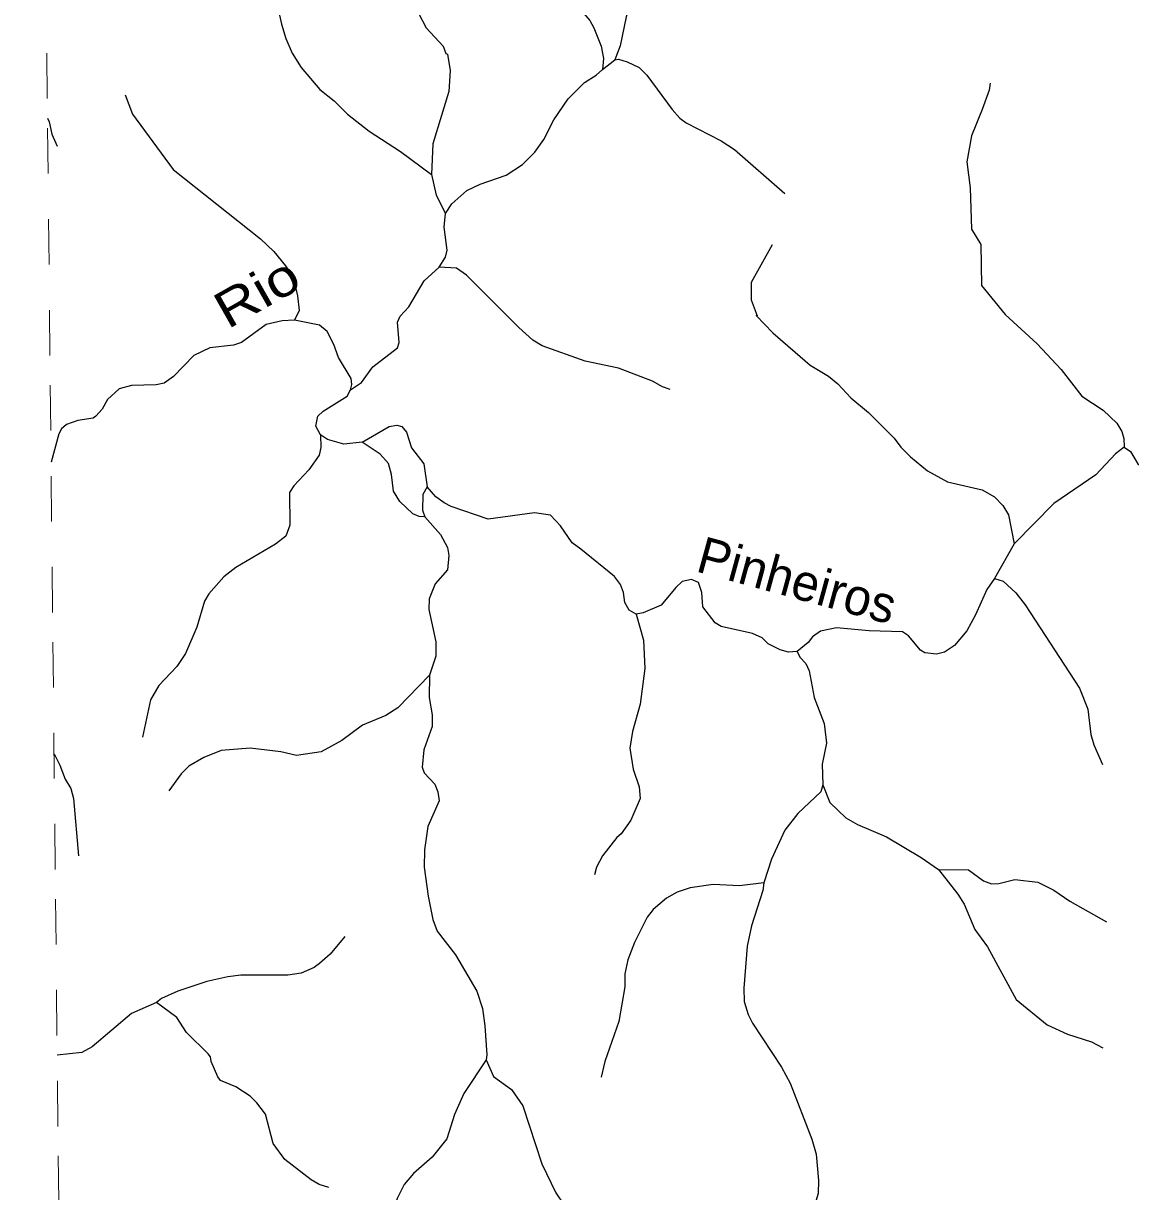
# Model space of a CAD drawing. Extents: x 346.5 to 372.4, y 7400.3 to 7428.2.
# Drawn here: x 346.55 to 348.985, y 7420.515 to 7423.084 of the extents above; entities that cross this region are included whole.
import ezdxf
from ezdxf.enums import TextEntityAlignment as Align

# ---------------------------------------------------------------- set-up
doc = ezdxf.new("R2010")
doc.units = 0
doc.header["$LTSCALE"] = 0.032
doc.linetypes.add('SHORT_DASHED', pattern=[2.7, 1.5, -1.2])
for name, color, linetype, lineweight in [('2', 7, 'Continuous', 25), ('53', 7, 'SHORT_DASHED', 13), ('7', 7, 'Continuous', 25)]:
    doc.layers.add(name, color=color, linetype=linetype, lineweight=lineweight)
doc.layers.add('61', color=7, linetype='Continuous')

msp = doc.modelspace()

# ---------------------------------------------------------------- linework, layer by layer
at = {"layer": '2'}
msp.add_lwpolyline([(347.2945, 7422.163), (347.3542, 7422.1973), (347.3709, 7422.2), (347.3817, 7422.1975), (347.392, 7422.1852), (347.4031, 7422.1505), (347.43, 7422.115), (347.4378, 7422.0645), (347.4279, 7422.0477), (347.4272, 7422.0132), (347.4327, 7421.9988), (347.4198, 7421.9995), (347.4059, 7422.0057), (347.3778, 7422.0327), (347.3637, 7422.0549), (347.3591, 7422.0917), (347.3525, 7422.116), (347.3346, 7422.1365)], close=True, dxfattribs=at)
at = {"layer": '53'}
msp.add_lwpolyline([(346.6314, 7420.0936), (346.6255, 7420.6585), (346.6197, 7421.2235), (346.6138, 7421.7885), (346.608, 7422.3534), (346.6021, 7422.9184), (346.5963, 7423.4833), (346.5904, 7424.0483), (346.5846, 7424.6132), (346.5787, 7425.1782), (346.5729, 7425.7431), (346.567, 7426.3081), (346.5612, 7426.873), (346.5553, 7427.438), (346.5495, 7428.0029)], dxfattribs=at)
at = {"layer": '7'}
for points in [[(347.5316, 7423.518), (347.538, 7423.5013), (347.5826, 7423.4375), (347.6216, 7423.3714), (347.6822, 7423.31), (347.6958, 7423.2813), (347.7205, 7423.1953), (347.7555, 7423.1379), (347.7954, 7423.0901), (347.8041, 7423.0741), (347.8201, 7423.0335), (347.8254, 7423.0065), (347.8232, 7422.982)], [(347.0399, 7423.475), (347.0152, 7423.4057), (347.012, 7423.3754), (347.0168, 7423.3307), (347.0263, 7423.302), (347.0486, 7423.259), (347.0678, 7423.2303), (347.1004, 7423.1586), (347.1172, 7423.0821), (347.1267, 7423.0502), (347.1411, 7423.0183), (347.1602, 7422.9865), (347.2016, 7422.9386), (347.2335, 7422.9131), (347.2622, 7422.8844), (347.31, 7422.847), (347.3794, 7422.8023), (347.4474, 7422.7514)], [(347.2678, 7423.4208), (347.2997, 7423.3132), (347.3132, 7423.2845), (347.3308, 7423.2558), (347.3594, 7423.2224), (347.3889, 7423.1793), (347.4184, 7423.106), (347.4352, 7423.0741), (347.4726, 7423.0335), (347.479, 7423.0175), (347.4822, 7423.0159), (347.4885, 7422.9801), (347.4854, 7422.9339), (347.4503, 7422.8191), (347.4474, 7422.7514)], [(347.9444, 7423.1931), (347.931, 7423.1802), (347.9179, 7423.1754), (347.8878, 7423.1387), (347.8751, 7423.098), (347.8623, 7423.0343), (347.8502, 7423.0037)], [(347.4782, 7422.6659), (347.4917, 7422.6868), (347.5252, 7422.7163), (347.5539, 7422.7298), (347.6113, 7422.7498), (347.6471, 7422.7737), (347.6742, 7422.8008), (347.6942, 7422.8287), (347.7165, 7422.8717), (347.7476, 7422.9179), (347.7834, 7422.9538), (347.8097, 7422.9697), (347.8232, 7422.982), (347.8502, 7423.0037)], [(347.8502, 7423.0037), (347.8583, 7423.0047), (347.8775, 7422.9992), (347.9038, 7422.9865), (347.9205, 7422.9697), (347.9763, 7422.894), (347.9938, 7422.8749), (348.0074, 7422.8653), (348.0847, 7422.8255), (348.1134, 7422.8063), (348.2241, 7422.7099)], [(348.676, 7422.9522), (348.6736, 7422.937), (348.6585, 7422.894), (348.6346, 7422.8366), (348.625, 7422.7793), (348.6322, 7422.7219), (348.6346, 7422.631), (348.6553, 7422.5975), (348.6569, 7422.5075), (348.7087, 7422.4437), (348.7796, 7422.3792), (348.8322, 7422.3226), (348.8776, 7422.2644), (348.9247, 7422.2333), (348.9549, 7422.2046), (348.9653, 7422.1863), (348.9697, 7422.1709), (348.9704, 7422.1516)], [(346.7737, 7422.9267), (346.7896, 7422.8844), (346.8789, 7422.7625), (347.071, 7422.6103), (347.1004, 7422.5824), (347.1259, 7422.5505), (347.1387, 7422.5322), (347.1451, 7422.5163), (347.1522, 7422.4844), (347.1562, 7422.4525), (347.1462, 7422.4315)], [(346.6026, 7422.875), (346.6066, 7422.8673), (346.6119, 7422.8398), (346.6239, 7422.8135)], [(347.4474, 7422.7514), (347.4575, 7422.7059), (347.4782, 7422.6659)], [(347.4638, 7422.5474), (347.4782, 7422.5697), (347.4814, 7422.5848), (347.475, 7422.6358), (347.4782, 7422.6659)], [(348.1963, 7422.5967), (348.15, 7422.5139), (348.15, 7422.4756), (348.1636, 7422.4405), (348.1612, 7422.4413), (348.1978, 7422.4031), (348.2799, 7422.3322), (348.3206, 7422.3082), (348.3413, 7422.2915), (348.3692, 7422.2604), (348.4082, 7422.2278), (348.4648, 7422.172), (348.4792, 7422.152), (348.5007, 7422.1305), (348.5381, 7422.1002), (348.582, 7422.0755), (348.6585, 7422.058), (348.6856, 7422.0429), (348.7039, 7422.0237), (348.7166, 7422.003), (348.7285, 7421.9397)], [(347.2692, 7422.2783), (347.2933, 7422.2939), (347.318, 7422.3282), (347.3722, 7422.3704), (347.3762, 7422.3824), (347.3722, 7422.427), (347.3786, 7422.4397), (347.3977, 7422.4605), (347.4312, 7422.5178), (347.4638, 7422.5474)], [(347.9723, 7422.2788), (347.9556, 7422.2843), (347.9333, 7422.2971), (347.8584, 7422.3258), (347.785, 7422.3409), (347.691, 7422.3744), (347.6703, 7422.3871), (347.6392, 7422.415), (347.5244, 7422.5298), (347.5021, 7422.5457), (347.4638, 7422.5474)], [(347.1462, 7422.4315), (347.1188, 7422.4294), (347.0837, 7422.4214), (347.0295, 7422.3823), (347.012, 7422.376), (346.9594, 7422.3704), (346.9243, 7422.3537), (346.8797, 7422.3075), (346.859, 7422.2923), (346.8414, 7422.2891), (346.7873, 7422.2875), (346.7601, 7422.2803), (346.7346, 7422.2564), (346.7227, 7422.2357), (346.7091, 7422.2198), (346.7028, 7422.2158), (346.6693, 7422.2102), (346.6446, 7422.2014), (346.6334, 7422.1919), (346.6278, 7422.1815), (346.6104, 7422.1191)], [(347.2692, 7422.2783), (347.272, 7422.29), (347.2702, 7422.3027), (347.2423, 7422.3489), (347.2327, 7422.3776), (347.2176, 7422.4063), (347.2009, 7422.4198), (347.1462, 7422.4315)], [(347.2028, 7422.1787), (347.1929, 7422.1983), (347.1969, 7422.2198), (347.2088, 7422.2309), (347.2614, 7422.2644), (347.2692, 7422.2783)], [(347.2028, 7422.1787), (347.2038, 7422.1514), (347.2001, 7422.1345), (347.1777, 7422.1018), (347.1443, 7422.0668), (347.1347, 7422.0524), (347.1355, 7421.9807), (347.1267, 7421.956), (347.1044, 7421.9385), (347.0168, 7421.8874), (346.9905, 7421.8667), (346.9578, 7421.8293), (346.9482, 7421.8134), (346.9307, 7421.756), (346.906, 7421.6986), (346.8869, 7421.6699), (346.8478, 7421.6277), (346.8295, 7421.5966), (346.8112, 7421.5145)], [(347.2945, 7422.163), (347.2543, 7422.1584), (347.2187, 7422.1691), (347.2028, 7422.1787)], [(348.9704, 7422.1516), (348.9517, 7422.1369), (348.9087, 7422.0914), (348.8163, 7422.0277), (348.7285, 7421.9397), (348.6857, 7421.8634)], [(348.9704, 7422.1516), (348.9849, 7422.1426), (349.0012, 7422.1138), (349.0171, 7422.1114), (349.0474, 7422.1202), (349.0617, 7422.1186), (349.0689, 7422.1138), (349.0737, 7422.1082), (349.0737, 7422.0827), (349.0681, 7422.0739), (349.0665, 7422.0636), (349.0705, 7422.0493), (349.088, 7422.0341), (349.1207, 7422.0325), (349.1367, 7422.0325), (349.1597, 7422.0261), (349.1812, 7422.0097), (349.1894, 7422.0055), (349.2092, 7422.004)], [(347.8971, 7421.7844), (347.8818, 7421.7938), (347.8727, 7421.8102), (347.8695, 7421.8325), (347.8631, 7421.85), (347.8496, 7421.8675), (347.7755, 7421.9273), (347.7563, 7421.9416), (347.7308, 7421.9791), (347.7093, 7422.0022), (347.6735, 7422.0078), (347.5722, 7421.9934), (347.4902, 7422.0213), (347.475, 7422.0293), (347.4567, 7422.0429), (347.4378, 7422.0645)], [(347.4327, 7421.9988), (347.467, 7421.96), (347.4822, 7421.9313), (347.4854, 7421.9138), (347.4822, 7421.8819), (347.4551, 7421.8516), (347.4423, 7421.8181), (347.4415, 7421.795), (347.4567, 7421.7241), (347.4567, 7421.6922), (347.4426, 7421.6504)], [(348.2514, 7421.7026), (348.2328, 7421.7013), (348.2138, 7421.7065), (348.1875, 7421.7193), (348.1747, 7421.7328), (348.1532, 7421.7424), (348.0847, 7421.7575), (348.0711, 7421.7655), (348.044, 7421.8006), (348.0416, 7421.8325), (348.0345, 7421.854), (348.0193, 7421.8611), (347.9986, 7421.8564), (347.9843, 7421.8436), (347.9524, 7421.8046), (347.9125, 7421.7878), (347.8971, 7421.7844)], [(348.6857, 7421.8634), (348.6686, 7421.8389), (348.6441, 7421.7831), (348.625, 7421.748), (348.5979, 7421.7161), (348.5756, 7421.701), (348.5581, 7421.697), (348.5326, 7421.6994), (348.523, 7421.7057), (348.4967, 7421.7368), (348.4831, 7421.7456), (348.4098, 7421.748), (348.3381, 7421.7544), (348.303, 7421.7472), (348.2855, 7421.7352), (348.2755, 7421.7226), (348.2514, 7421.7026)], [(348.6857, 7421.8634), (348.7047, 7421.8572), (348.7326, 7421.8317), (348.7533, 7421.8054), (348.8728, 7421.6221), (348.8912, 7421.5759), (348.8976, 7421.5201), (348.9039, 7421.4978), (348.9231, 7421.4539)], [(347.8971, 7421.7844), (347.9133, 7421.7273), (347.9165, 7421.6651), (347.9062, 7421.587), (347.8894, 7421.5265), (347.8838, 7421.4898), (347.891, 7421.4436), (347.9038, 7421.4053), (347.9062, 7421.3798), (347.8854, 7421.332), (347.8647, 7421.3017), (347.8551, 7421.2937), (347.8233, 7421.2531), (347.8105, 7421.2284), (347.8058, 7421.2117)], [(348.2514, 7421.7026), (348.2575, 7421.6905), (348.2703, 7421.6763), (348.2779, 7421.6603), (348.2887, 7421.6014), (348.311, 7421.544), (348.3158, 7421.501), (348.3062, 7421.4547), (348.308, 7421.4097)], [(347.4426, 7421.6504), (347.373, 7421.579), (347.3467, 7421.5623), (347.2957, 7421.5408), (347.2503, 7421.5073), (347.2049, 7421.4818), (347.1506, 7421.4738), (347.1156, 7421.4818), (347.0487, 7421.4898), (346.9849, 7421.485), (346.9466, 7421.4699), (346.9132, 7421.4507), (346.8964, 7421.434), (346.8693, 7421.3965)], [(347.4426, 7421.6504), (347.4423, 7421.6014), (347.4487, 7421.5631), (347.4487, 7421.5376), (347.4304, 7421.4866), (347.4264, 7421.4484), (347.4312, 7421.4356), (347.4543, 7421.4109), (347.4615, 7421.3942), (347.4638, 7421.3742), (347.4391, 7421.3177), (347.432, 7421.2666), (347.4312, 7421.2284), (347.4399, 7421.1646), (347.4503, 7421.1136), (347.4599, 7421.0881), (347.4997, 7421.0355), (347.5467, 7420.9558), (347.5595, 7420.9176), (347.5643, 7420.8793), (347.569, 7420.8156), (347.5673, 7420.8051)], [(346.617, 7421.4773), (346.6295, 7421.4526), (346.6414, 7421.4221), (346.6541, 7421.4013), (346.6597, 7421.3798), (346.6709, 7421.2531)], [(348.308, 7421.4097), (348.3035, 7421.394), (348.2528, 7421.3463), (348.2241, 7421.3097), (348.1954, 7421.2459), (348.1783, 7421.1943)], [(348.308, 7421.4097), (348.3237, 7421.3703), (348.3588, 7421.3368), (348.3843, 7421.3224), (348.4481, 7421.2953), (348.5246, 7421.2499), (348.5623, 7421.2237)], [(348.5623, 7421.2237), (348.6282, 7421.2228), (348.6617, 7421.1981), (348.6792, 7421.1917), (348.6951, 7421.1925), (348.7302, 7421.2013), (348.7812, 7421.1957), (348.8163, 7421.1782), (348.8513, 7421.1535), (348.9318, 7421.1081)], [(348.5623, 7421.2237), (348.6051, 7421.1694), (348.6186, 7421.1471), (348.6425, 7421.0913), (348.6704, 7421.0531), (348.7334, 7420.9375), (348.8011, 7420.8817), (348.8458, 7420.861), (348.8992, 7420.8443), (348.9239, 7420.8315)], [(348.1783, 7421.1943), (348.1245, 7421.1877), (348.0671, 7421.1901), (348.0161, 7421.183), (347.9875, 7421.1734), (347.9643, 7421.1606), (347.9348, 7421.1351), (347.9213, 7421.1184), (347.8934, 7421.0626), (347.8791, 7421.0244), (347.8727, 7420.9941), (347.8727, 7420.9654), (347.8591, 7420.8889), (347.8288, 7420.8012), (347.8201, 7420.767)], [(348.1783, 7421.1943), (348.1763, 7421.1774), (348.1508, 7421.0993), (348.1413, 7421.0547), (348.1341, 7420.9622), (348.1349, 7420.9335), (348.1436, 7420.9048), (348.1532, 7420.8857), (348.217, 7420.7885), (348.2361, 7420.7534), (348.2839, 7420.6307), (348.2935, 7420.5972), (348.2983, 7420.5398), (348.2975, 7420.5111), (348.2855, 7420.4697), (348.2855, 7420.4378), (348.2903, 7420.3948), (348.299, 7420.3502), (348.3015, 7420.3191)], [(347.2567, 7421.0762), (347.224, 7421.0371), (347.2009, 7421.0164), (347.1889, 7421.0076), (347.1602, 7420.9957), (347.1315, 7420.9909), (347.0279, 7420.9909), (346.9992, 7420.9877), (346.953, 7420.9773), (346.8893, 7420.9558), (346.8533, 7420.9399), (346.8424, 7420.9312)], [(346.8424, 7420.9312), (346.7873, 7420.9064), (346.7012, 7420.8331), (346.6781, 7420.8211), (346.6239, 7420.8155)], [(347.2216, 7420.5239), (347.2001, 7420.5311), (347.1825, 7420.5414), (347.1243, 7420.5861), (347.0988, 7420.6211), (347.0821, 7420.6857), (347.063, 7420.7104), (347.0487, 7420.7247), (347.0168, 7420.7454), (346.9833, 7420.7598), (346.9769, 7420.7678), (346.9626, 7420.8012), (346.961, 7420.8116), (346.9562, 7420.8179), (346.9084, 7420.865), (346.8869, 7420.8976), (346.8424, 7420.9312)], [(347.5673, 7420.8051), (347.518, 7420.7311), (347.4981, 7420.6849), (347.4806, 7420.6315), (347.4487, 7420.5908), (347.4073, 7420.555), (347.3873, 7420.5311), (347.3714, 7420.5), (347.3578, 7420.457), (347.3387, 7420.4115)], [(347.5673, 7420.8051), (347.5834, 7420.7685), (347.6232, 7420.7399), (347.6479, 7420.704), (347.6902, 7420.5765), (347.7205, 7420.5127), (347.7372, 7420.4872), (347.7507, 7420.4737), (347.7802, 7420.4569), (347.8823, 7420.4394), (347.8966, 7420.4298), (347.9181, 7420.4083), (347.9811, 7420.3725), (348.0504, 7420.3095)]]:
    msp.add_lwpolyline(points, dxfattribs=at)

# ---------------------------------------------------------------- texts
at = {"layer": '61', "width": 1.2}
msp.add_text('Rio', height=0.08, rotation=29.541, dxfattribs=at).set_placement((347.0827, 7422.4577), align=Align.CENTER)
at = {"layer": '61'}
msp.add_text('Pinheiros', height=0.08, rotation=344.712, dxfattribs=at).set_placement((348.241, 7421.8207), align=Align.CENTER)

doc.saveas('drawing.dxf')
